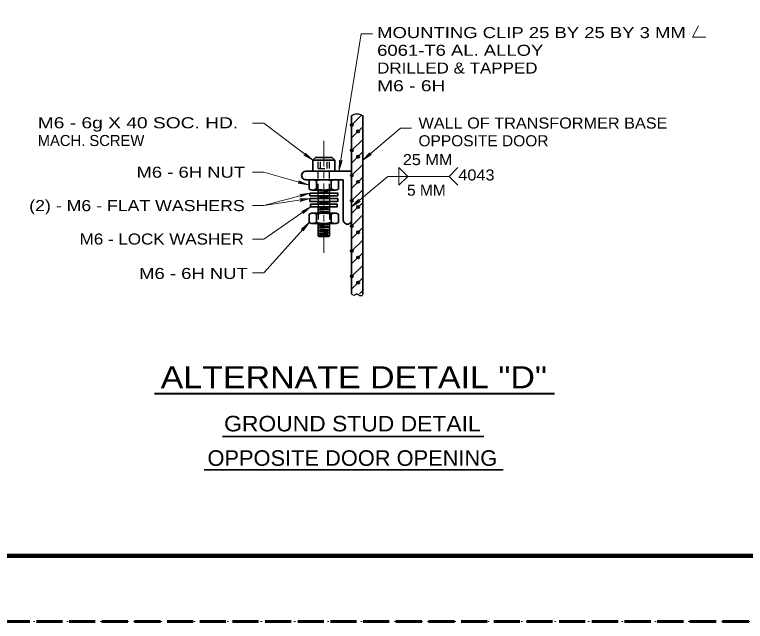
# Model space of a CAD drawing. Extents: x 312583 to 312854, y 144419 to 144597.
# Drawn here: x 312751.7 to 312802, y 144418.6 to 144460.3 of the extents above; entities that cross this region are included whole.
import ezdxf
from ezdxf.enums import TextEntityAlignment as Align

# ---------------------------------------------------------------- set-up
doc = ezdxf.new("R2010")
doc.units = 0
doc.header["$LTSCALE"] = 0.3
doc.header["$PDMODE"] = 32
doc.header["$PDSIZE"] = 0.15
for name, pattern in [('DOTTED', [1.5, 0.3, -1.2]), ('LONG_DASH_SHORT_DASH', [9.9, 6, -1.2, 1.5, -1.2]), ('LONG_DASHED', [7.5, 6, -1.5]), ('SHORT_DASHED', [2.7, 1.5, -1.2])]:
    doc.linetypes.add(name, pattern=pattern)
for name, color, linetype, lineweight in [('1', 7, 'Continuous', 40), ('2', 7, 'Continuous', 13), ('62', 7, 'DOTTED', 13), ('63', 7, 'LONG_DASHED', 60)]:
    doc.layers.add(name, color=color, linetype=linetype, lineweight=lineweight)

msp = doc.modelspace()

# ---------------------------------------------------------------- linework, layer by layer
at = {"layer": '1', "lineweight": 35}
for p, q in [((312774.9093, 144441.1228), (312774.9093, 144453.3895)), ((312775.676, 144441.1228), (312775.676, 144453.3895)), ((312773.5676, 144450.5145), (312773.7593, 144450.3228)), ((312772.226, 144449.5562), (312772.226, 144450.3228)), ((312774.9093, 144449.5562), (312771.7506, 144449.5562)), ((312774.3343, 144448.9812), (312771.743, 144448.9812)), ((312772.2106, 144448.9812), (312772.9926, 144448.9812)), ((312773.7746, 144448.9812), (312772.9926, 144448.9812)), ((312774.3343, 144446.2058), (312774.3343, 144448.9812)), ((312771.9883, 144448.9122), (312771.9883, 144448.3372)), ((312772.4866, 144448.9122), (312772.4866, 144448.3372)), ((312773.4986, 144448.9122), (312773.4986, 144448.3372)), ((312773.997, 144448.9122), (312773.997, 144448.3372)), ((312772.2106, 144448.2682), (312772.9926, 144448.2682)), ((312772.6093, 144448.2528), (312772.6093, 144448.0612)), ((312773.7746, 144448.2682), (312772.9926, 144448.2682)), ((312773.376, 144448.2528), (312773.376, 144448.0612)), ((312772.6093, 144447.8695), (312772.6093, 144447.6778)), ((312772.6093, 144447.4938), (312772.6093, 144447.2945)), ((312773.376, 144447.8695), (312773.376, 144447.6778)), ((312773.376, 144447.4938), (312773.376, 144447.2945)), ((312772.6093, 144447.1105), (312772.6093, 144446.6812)), ((312773.376, 144447.1105), (312773.376, 144446.6812)), ((312771.9883, 144446.6122), (312771.9883, 144446.0372)), ((312772.2106, 144446.6812), (312772.9926, 144446.6812)), ((312772.4866, 144446.6122), (312772.4866, 144446.0372)), ((312773.7746, 144446.6812), (312772.9926, 144446.6812)), ((312773.4986, 144446.6122), (312773.4986, 144446.0372)), ((312773.997, 144446.6122), (312773.997, 144446.0372)), ((312772.2106, 144445.9682), (312772.9926, 144445.9682)), ((312772.6093, 144445.9682), (312772.6093, 144445.1478)), ((312773.7746, 144445.9682), (312772.9926, 144445.9682)), ((312773.376, 144445.9682), (312773.376, 144445.1478)), ((312772.6093, 144445.1478), (312772.9926, 144445.1478)), ((312773.376, 144445.1478), (312772.9926, 144445.1478))]:
    msp.add_line(p, q, dxfattribs=at)
at = {"layer": '1', "lineweight": 13}
for p, q in [((312774.9093, 144452.7225), (312775.5763, 144453.3895)), ((312774.9093, 144451.8562), (312775.676, 144452.6228)), ((312774.9093, 144450.9898), (312775.676, 144451.7565)), ((312774.9093, 144450.1235), (312775.676, 144450.8902)), ((312774.9093, 144449.2572), (312775.676, 144450.0238)), ((312774.9093, 144448.3832), (312775.676, 144449.1575)), ((312774.9093, 144447.5245), (312775.676, 144448.2912)), ((312774.9093, 144446.6505), (312775.676, 144447.4172)), ((312774.9093, 144445.7842), (312775.676, 144446.5508)), ((312774.9093, 144444.9178), (312775.676, 144445.6845)), ((312774.9093, 144444.0515), (312775.676, 144444.8182)), ((312774.9093, 144443.1852), (312775.676, 144443.9518)), ((312774.9093, 144442.3188), (312775.676, 144443.0855)), ((312774.9093, 144441.4525), (312775.676, 144442.2192)), ((312775.4536, 144441.1228), (312775.676, 144441.3452))]:
    msp.add_line(p, q, dxfattribs=at)
at = {"layer": '1', "linetype": 'LONG_DASH_SHORT_DASH', "lineweight": 13}
msp.add_line((312772.9926, 144443.9442), (312772.9926, 144451.6492), dxfattribs=at)
at = {"layer": '1', "linetype": 'SHORT_DASHED', "lineweight": 25}
for p, q in [((312772.6093, 144449.7478), (312772.6093, 144450.5145)), ((312772.7703, 144449.7478), (312772.7703, 144450.5145)), ((312773.2303, 144449.7478), (312773.2303, 144450.5145)), ((312773.376, 144449.7478), (312773.376, 144450.5145)), ((312772.6093, 144449.7478), (312773.376, 144449.7478)), ((312772.6093, 144448.2528), (312772.6093, 144449.5562)), ((312773.376, 144448.2528), (312773.376, 144449.5562)), ((312772.6093, 144447.8695), (312772.6093, 144448.0612)), ((312773.376, 144447.8695), (312773.376, 144448.0612)), ((312772.6093, 144447.6778), (312772.6093, 144447.4938)), ((312773.376, 144447.6778), (312773.376, 144447.4938)), ((312772.6093, 144447.2945), (312772.6093, 144447.1105)), ((312773.376, 144447.2945), (312773.376, 144447.1105)), ((312772.6093, 144446.6812), (312772.6093, 144445.9682)), ((312773.376, 144446.6812), (312773.376, 144445.9682))]:
    msp.add_line(p, q, dxfattribs=at)
at = {"layer": '1', "lineweight": 25}
for p, q in [((312772.7013, 144448.1532), (312772.9926, 144448.1532)), ((312773.284, 144448.1532), (312772.9926, 144448.1532)), ((312772.7013, 144447.7775), (312772.9926, 144447.7775)), ((312772.7013, 144447.7775), (312773.284, 144447.7775)), ((312773.284, 144447.7775), (312772.9926, 144447.7775)), ((312772.7013, 144447.3942), (312773.284, 144447.3942)), ((312772.7013, 144447.0108), (312773.284, 144447.0108)), ((312772.6093, 144446.9188), (312772.9926, 144446.9188)), ((312772.6093, 144446.7272), (312772.9926, 144446.7272)), ((312772.7013, 144446.8192), (312773.284, 144446.8192)), ((312773.376, 144446.9188), (312772.9926, 144446.9188)), ((312773.376, 144446.7272), (312772.9926, 144446.7272)), ((312772.6093, 144445.8762), (312772.9926, 144445.8762)), ((312772.6093, 144445.6845), (312772.9926, 144445.6845)), ((312772.6093, 144445.4928), (312772.9926, 144445.4928)), ((312772.7013, 144445.7765), (312773.284, 144445.7765)), ((312772.7013, 144445.5848), (312773.284, 144445.5848)), ((312773.376, 144445.8762), (312772.9926, 144445.8762)), ((312773.376, 144445.6845), (312772.9926, 144445.6845)), ((312773.376, 144445.4928), (312772.9926, 144445.4928)), ((312772.6093, 144445.3012), (312772.9926, 144445.3012)), ((312772.7013, 144445.4085), (312773.284, 144445.4085)), ((312772.7013, 144445.2322), (312773.2763, 144445.2322)), ((312773.376, 144445.3012), (312772.9926, 144445.3012))]:
    msp.add_line(p, q, dxfattribs=at)
at = {"layer": '1', "lineweight": 158}
msp.add_line((312616.5, 144423.0846), (312849, 144423.0846), dxfattribs=at)
at = {"layer": '1', "lineweight": 35}
for points in [[(312773.5676, 144450.5145), (312772.4176, 144450.5145), (312772.226, 144450.3228)], [(312773.7593, 144449.5562), (312773.7593, 144450.3228), (312772.226, 144450.3228)], [(312772.6093, 144445.1478), (312772.6553, 144445.0788), (312772.9926, 144445.0788)], [(312773.376, 144445.1478), (312773.33, 144445.0788), (312772.9926, 144445.0788)]]:
    msp.add_lwpolyline(points, dxfattribs=at)
for points in [[(312772.0343, 144448.0612), (312772.0343, 144447.8695), (312773.951, 144447.8695), (312773.951, 144448.0612)], [(312772.0343, 144447.6778), (312772.0343, 144447.4862), (312773.951, 144447.4862), (312773.951, 144447.6778)], [(312772.088, 144447.2945), (312772.088, 144447.1105), (312773.905, 144447.1105), (312773.905, 144447.2945)]]:
    msp.add_lwpolyline(points, close=True, dxfattribs=at)
for centre, radius, start, end in [((312771.746, 144449.271), 0.2867, 89.69361, 270.30639), ((312772.2196, 144448.569), 0.415, 91.66257, 124.1297), ((312772.0192, 144447.8216), 1.1883, 66.63635, 78.22986), ((312773.0456, 144446.8411), 2.1446, 91.405, 105.00202), ((312772.9404, 144446.8411), 2.1446, 74.99798, 88.595), ((312773.9668, 144447.8216), 1.1883, 101.77014, 113.36365), ((312773.7664, 144448.569), 0.415, 55.8703, 88.33743), ((312772.2196, 144448.6834), 0.415, 235.8703, 268.33743), ((312772.0192, 144449.4308), 1.1883, 281.77014, 293.36365), ((312773.0456, 144450.4113), 2.1446, 254.99798, 268.595), ((312772.9404, 144450.4113), 2.1446, 271.405, 285.00202), ((312773.9668, 144449.4308), 1.1883, 246.63635, 258.22986), ((312773.7664, 144448.6834), 0.415, 271.66257, 304.1297), ((312772.2196, 144446.269), 0.415, 91.66257, 124.1297), ((312772.0192, 144445.5216), 1.1883, 66.63635, 78.22986), ((312773.0456, 144444.5411), 2.1446, 91.405, 105.00202), ((312772.9404, 144444.5411), 2.1446, 74.99798, 88.595), ((312773.9668, 144445.5216), 1.1883, 101.77014, 113.36365), ((312773.7664, 144446.269), 0.415, 55.8703, 88.33743), ((312772.2196, 144446.3834), 0.415, 235.8703, 268.33743), ((312772.0192, 144447.1308), 1.1883, 281.77014, 293.36365), ((312773.0456, 144448.1113), 2.1446, 254.99798, 268.595), ((312772.9404, 144448.1113), 2.1446, 271.405, 285.00202), ((312773.9668, 144447.1308), 1.1883, 246.63635, 258.22986), ((312773.7664, 144446.3834), 0.415, 271.66257, 304.1297), ((312774.6226, 144446.2043), 0.2867, 179.69361, 0.30639)]:
    msp.add_arc(centre, radius, start, end, dxfattribs=at)
at = {"layer": '1', "lineweight": 25}
for points in [[(312774.9093, 144453.3895), (312775.032, 144453.4662), (312775.2466, 144453.5122), (312775.3846, 144453.5122), (312775.676, 144453.3895)], [(312774.9093, 144441.1228), (312775.1316, 144441.0538), (312775.2466, 144441.1305), (312775.4076, 144441.0538), (312775.6683, 144441.0538), (312775.676, 144441.1228)]]:
    msp.add_spline(points, degree=3, dxfattribs=at)
at = {"layer": '1'}
for p in [(312774.9246, 144452.7378), (312775.354, 144452.3085), (312774.9246, 144451.0052), (312775.354, 144450.5682), (312774.9246, 144449.2725), (312775.354, 144448.8355), (312774.9246, 144447.5398), (312775.354, 144447.1028), (312774.9246, 144445.7995), (312775.354, 144445.3625), (312774.9246, 144444.0668), (312775.354, 144443.6298), (312774.9246, 144442.3265), (312775.354, 144441.8972)]:
    msp.add_point(p, dxfattribs=at)
at = {"layer": '2'}
for p, q in [((312798.3832, 144458.784), (312798.7818, 144459.5737)), ((312774.0506, 144449.6328), (312775.5763, 144459.0245)), ((312775.5763, 144459.0245), (312776.343, 144459.0245)), ((312798.3832, 144458.784), (312799.2878, 144458.784)), ((312768.8603, 144452.8605), (312768.0936, 144452.8605)), ((312768.8603, 144452.8605), (312772.226, 144450.3228)), ((312771.6203, 144450.6755), (312771.8503, 144450.6065)), ((312772.226, 144450.3228), (312771.6203, 144450.6755)), ((312771.72, 144450.8058), (312771.8503, 144450.6065)), ((312772.226, 144450.3228), (312771.72, 144450.8058)), ((312775.676, 144450.3228), (312776.1513, 144450.8365)), ((312775.676, 144450.3228), (312776.2586, 144450.7062)), ((312776.1513, 144450.8365), (312776.0363, 144450.6295)), ((312776.2586, 144450.7062), (312776.0363, 144450.6295)), ((312774.0506, 144449.6328), (312774.0813, 144450.3305)), ((312774.0506, 144449.6328), (312774.25, 144450.2998)), ((312774.0813, 144450.3305), (312774.1273, 144450.1005)), ((312774.25, 144450.2998), (312774.1273, 144450.1005)), ((312768.8603, 144449.4872), (312768.0936, 144449.4872)), ((312768.8603, 144449.4872), (312771.9193, 144448.6285)), ((312782.231, 144449.8245), (312781.6176, 144449.2112)), ((312782.231, 144448.5978), (312781.6176, 144449.2112)), ((312771.2293, 144448.7358), (312771.4593, 144448.7588)), ((312771.9193, 144448.6285), (312771.2293, 144448.7358)), ((312771.2753, 144448.8968), (312771.4593, 144448.7588)), ((312771.9193, 144448.6285), (312771.2753, 144448.8968)), ((312768.8603, 144447.1948), (312772.0343, 144448.0612)), ((312772.0343, 144448.0612), (312771.3443, 144447.9615)), ((312772.0343, 144448.0612), (312771.3903, 144447.7928)), ((312768.8603, 144447.1948), (312772.0343, 144447.6778)), ((312772.0343, 144447.6778), (312771.3366, 144447.6625)), ((312772.0343, 144447.6778), (312771.3366, 144447.6625)), ((312771.3366, 144447.6625), (312771.5666, 144447.6088)), ((312771.3366, 144447.6625), (312771.5666, 144447.6088)), ((312771.3443, 144447.9615), (312771.582, 144447.9385)), ((312772.0343, 144447.6778), (312771.3673, 144447.4862)), ((312772.0343, 144447.6778), (312771.3673, 144447.4862)), ((312771.3673, 144447.4862), (312771.5666, 144447.6088)), ((312771.3673, 144447.4862), (312771.5666, 144447.6088)), ((312771.3903, 144447.7928), (312771.582, 144447.9385)), ((312774.9093, 144447.1028), (312775.3846, 144447.6165)), ((312774.9093, 144447.1028), (312775.492, 144447.4862)), ((312775.3846, 144447.6165), (312775.2696, 144447.4095)), ((312775.492, 144447.4862), (312775.2696, 144447.4095)), ((312768.8603, 144447.1948), (312768.0936, 144447.1948)), ((312768.8603, 144444.8795), (312772.088, 144447.1105)), ((312772.088, 144447.1105), (312771.467, 144446.7885)), ((312772.088, 144447.1105), (312771.5666, 144446.6428)), ((312771.467, 144446.7885), (312771.697, 144446.8422)), ((312771.5666, 144446.6428), (312771.697, 144446.8422)), ((312768.8603, 144442.5642), (312771.9883, 144446.0372)), ((312771.9883, 144446.0372), (312771.4593, 144445.5772)), ((312771.9883, 144446.0372), (312771.582, 144445.4622)), ((312771.4593, 144445.5772), (312771.674, 144445.6845)), ((312771.582, 144445.4622), (312771.674, 144445.6845)), ((312768.8603, 144444.8795), (312768.0936, 144444.8795)), ((312768.8603, 144442.5642), (312768.0936, 144442.5642))]:
    msp.add_line(p, q, dxfattribs=at)
at = {"layer": '2', "lineweight": 40}
msp.add_line((312761.3458, 144434.2612), (312788.8807, 144434.2612), dxfattribs=at)
at = {"layer": '2', "lineweight": 35}
for p, q in [((312766.0128, 144431.3172), (312784.0191, 144431.3172)), ((312764.7517, 144429.0172), (312785.3503, 144429.0172))]:
    msp.add_line(p, q, dxfattribs=at)
at = {"layer": '2'}
for points in [[(312775.676, 144450.3228), (312778.2673, 144452.5232), (312779.034, 144452.5232)], [(312778.16, 144449.2112), (312778.16, 144449.8245), (312778.7733, 144449.2112)], [(312774.9093, 144447.1028), (312777.3933, 144449.2112), (312778.16, 144449.2112), (312781.6176, 144449.2112)], [(312778.16, 144449.2112), (312778.16, 144448.5978), (312778.7733, 144449.2112)]]:
    msp.add_lwpolyline(points, dxfattribs=at)
at = {"layer": '62'}
msp.add_lwpolyline([(312601.2, 144418.5846), (312853.5, 144418.5846), (312853.5, 144596.7846)], dxfattribs=at)
at = {"layer": '63'}
msp.add_line((312851.75, 144418.5846), (312583.526, 144418.5846), dxfattribs=at)

# ---------------------------------------------------------------- texts
at = {"layer": '2'}
for s, width, p in [('MOUNTING CLIP 25 BY 25 BY 3 MM', 1.25, (312776.665, 144458.7245)), ('6061-T6 AL. ALLOY', 1.25, (312776.665, 144457.5045)), ('DRILLED & TAPPED', 1.15, (312776.665, 144456.2845)), ('M6 - 6H', 1.3, (312776.665, 144455.0645)), ('M6 - 6g X 40 SOC. HD.', 1.3, (312753.2964, 144452.5167)), ('WALL OF TRANSFORMER BASE', 1.1, (312779.5108, 144452.4983)), ('OPPOSITE DOOR', 1.05, (312779.5108, 144451.2783)), ('25 MM', 1.1, (312778.4338, 144449.982)), ('M6 - 6H NUT', 1.25, (312760.0946, 144449.1163)), ('4043', 1.1, (312782.2587, 144448.9246)), ('5 MM', 1.05, (312778.721, 144447.8786)), ('(2) - M6 - FLAT WASHERS', 1.2, (312752.709, 144446.8174)), (' M6 - LOCK WASHER', 1.15, (312755.8602, 144444.5175)), ('M6 - 6H NUT', 1.25, (312760.2769, 144442.1473))]:
    msp.add_text(s, height=0.76, dxfattribs=dict(at, width=width)).set_placement(p)
msp.add_text('MACH. SCREW', height=0.76, dxfattribs=at).set_placement((312753.2964, 144451.2967))
for s, height, width, p in [('ALTERNATE DETAIL "D"', 1.52, 1.15, (312775.0591, 144434.6265)), ('GROUND STUD DETAIL', 1.07, 1.1, (312774.9606, 144431.6589)), ('OPPOSITE DOOR OPENING', 1.07, 1.05, (312774.9586, 144429.2887))]:
    msp.add_text(s, height=height, dxfattribs=dict(at, width=width)).set_placement(p, align=Align.CENTER)

doc.saveas('drawing.dxf')
